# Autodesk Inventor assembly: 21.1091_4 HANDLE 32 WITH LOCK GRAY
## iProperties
Created: 2007-03
Part Number: 21.1091_4 HANDLE 32 WITH LOCK GRAY
Document SubType Name: Assembly
Designer: Andy Moles
Translation Standard: STEP AP214IS
File Name: 1000-U368_ASM
Preprocessor: PRO/ENGINEER BY PARAMETRIC TECHNOLOGY CORPORATION, 2003200
Postprocessor: Build: 344b, Release: 11 SP2 - Date: Fri 08/18/2006
Sent Units: MILLIMETERS
Uncertainty: 0.02000220415476
Author: Andy Moles
